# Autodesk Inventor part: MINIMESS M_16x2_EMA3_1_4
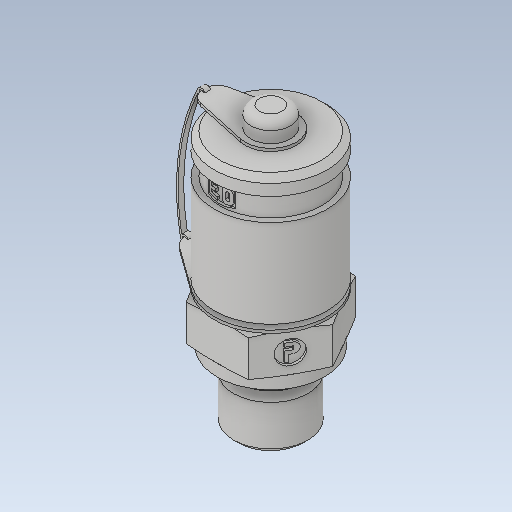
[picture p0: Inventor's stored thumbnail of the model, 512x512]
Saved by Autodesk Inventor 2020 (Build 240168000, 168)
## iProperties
DataBaseUnit: MM
Part Number: MINIMESS M_16x2_EMA3_1_4
Material: Generico
Document SubType Name: Modeling
Designer: carlo
Density: 1 g/cm^3
Appearance: Default
Author: carlo
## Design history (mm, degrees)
derived "MINIMESS M_16x2_EMA3_1_4.ipt"
node "Piano di lavoro1"
node "Piano di lavoro2"
node "Asse di lavoro1"
feature "Importato1::MINIMESS M_16x2_EMA3_1_4.ipt" dims "d0" = 10
tag "Lavorazione contrassegno1"
node "Solido1"
other parameters: "d1" = 0, "d2" = 0
